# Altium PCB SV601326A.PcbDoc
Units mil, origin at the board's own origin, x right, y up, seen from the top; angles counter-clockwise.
Board outline 2370 x 1275 mil, 4 copper layers (Top Layer, Signal Layer 1, Signal Layer 2, Bottom Layer), stack 61.2 mil thick; 63 components, 27 nets, 159 pads, 280 vias.
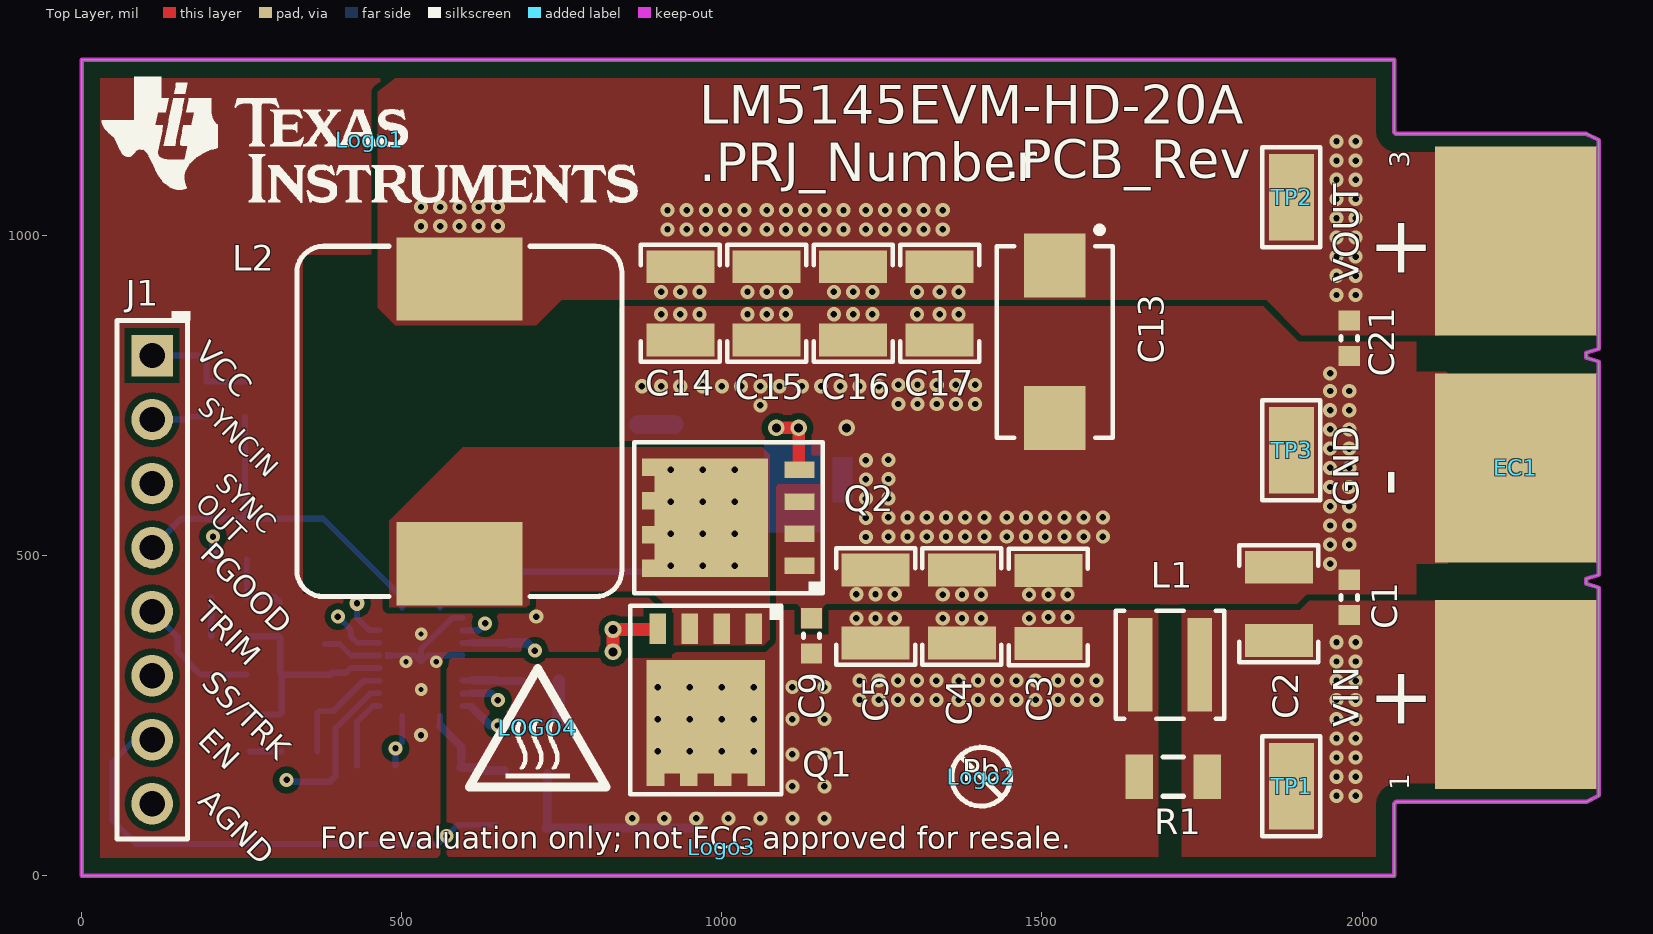
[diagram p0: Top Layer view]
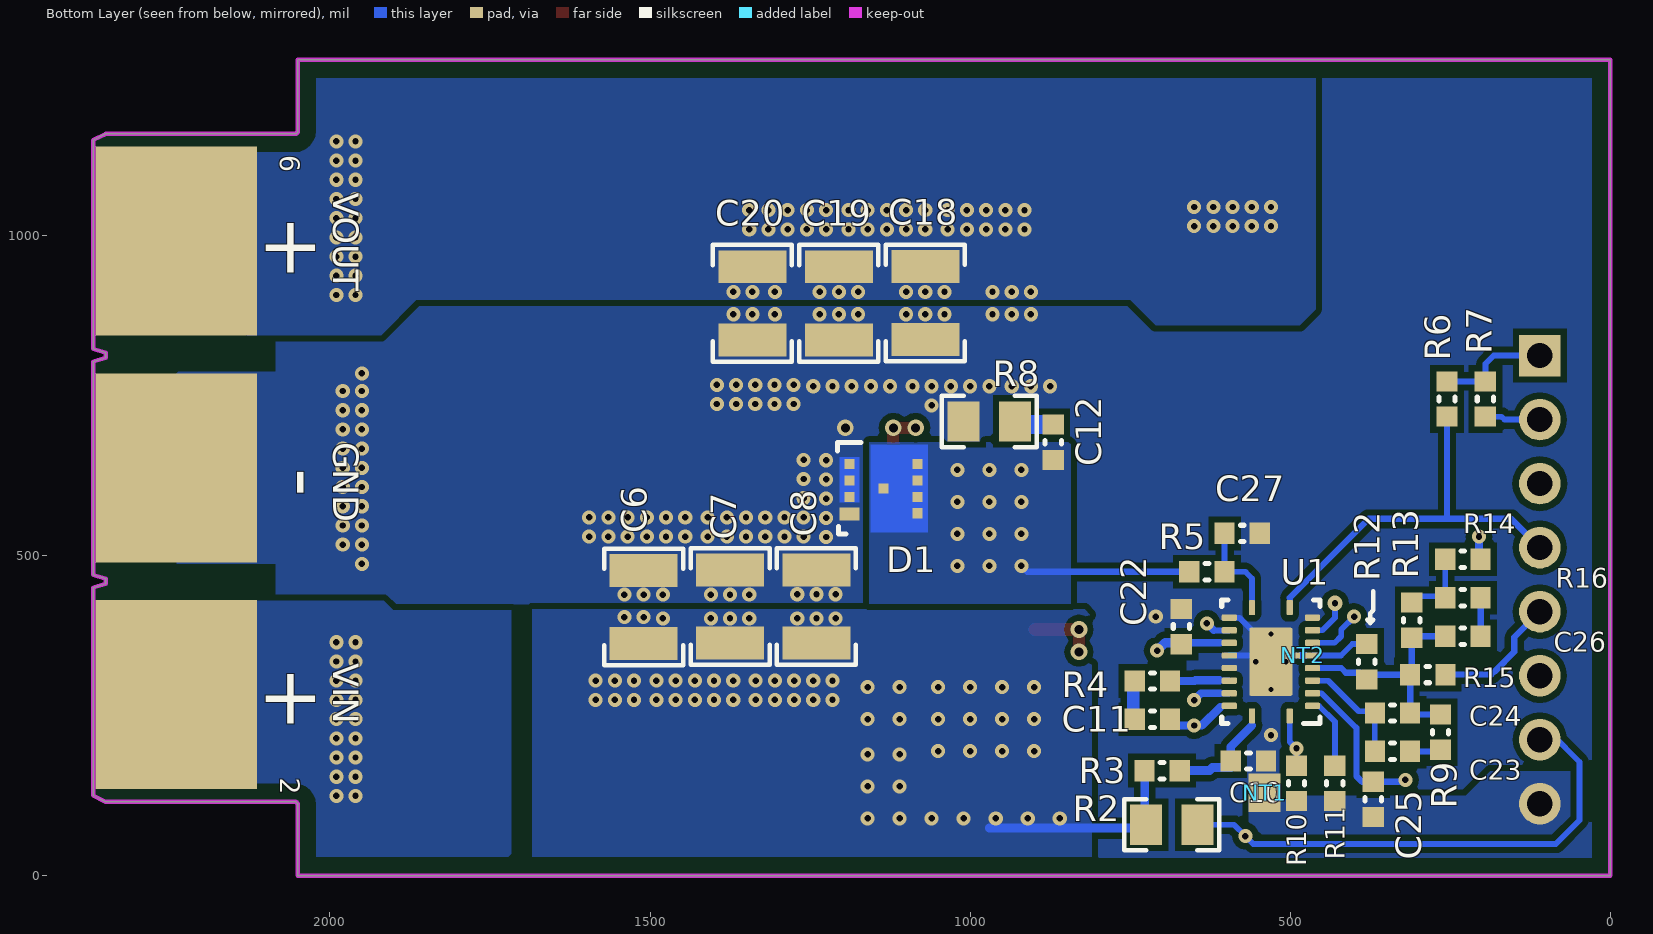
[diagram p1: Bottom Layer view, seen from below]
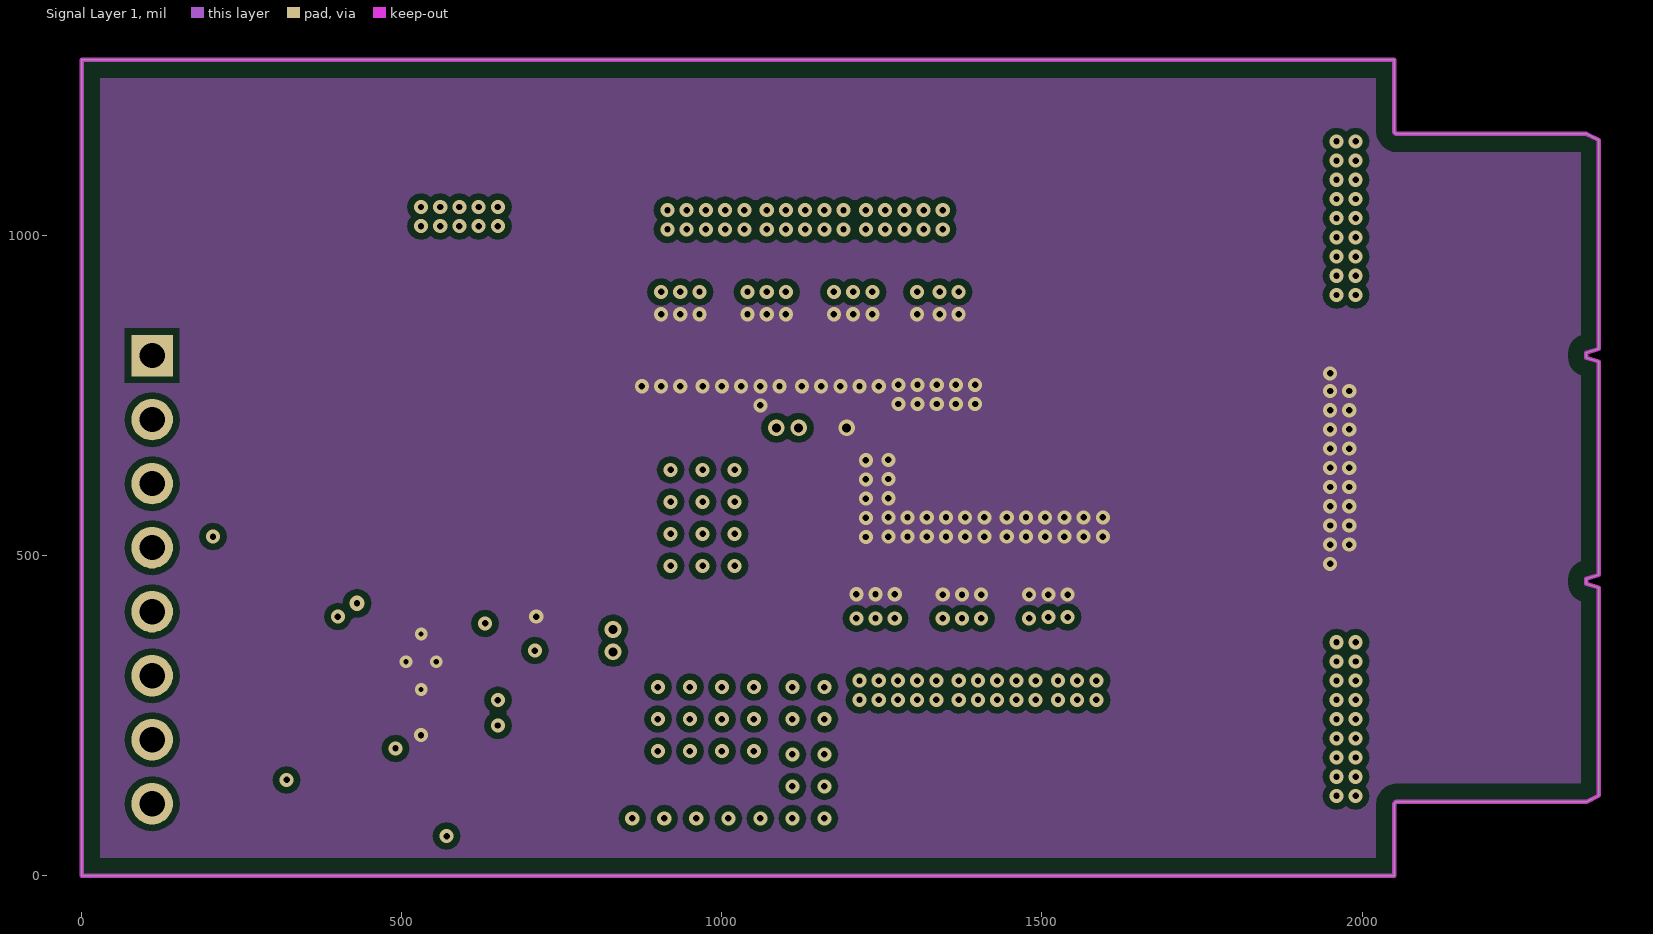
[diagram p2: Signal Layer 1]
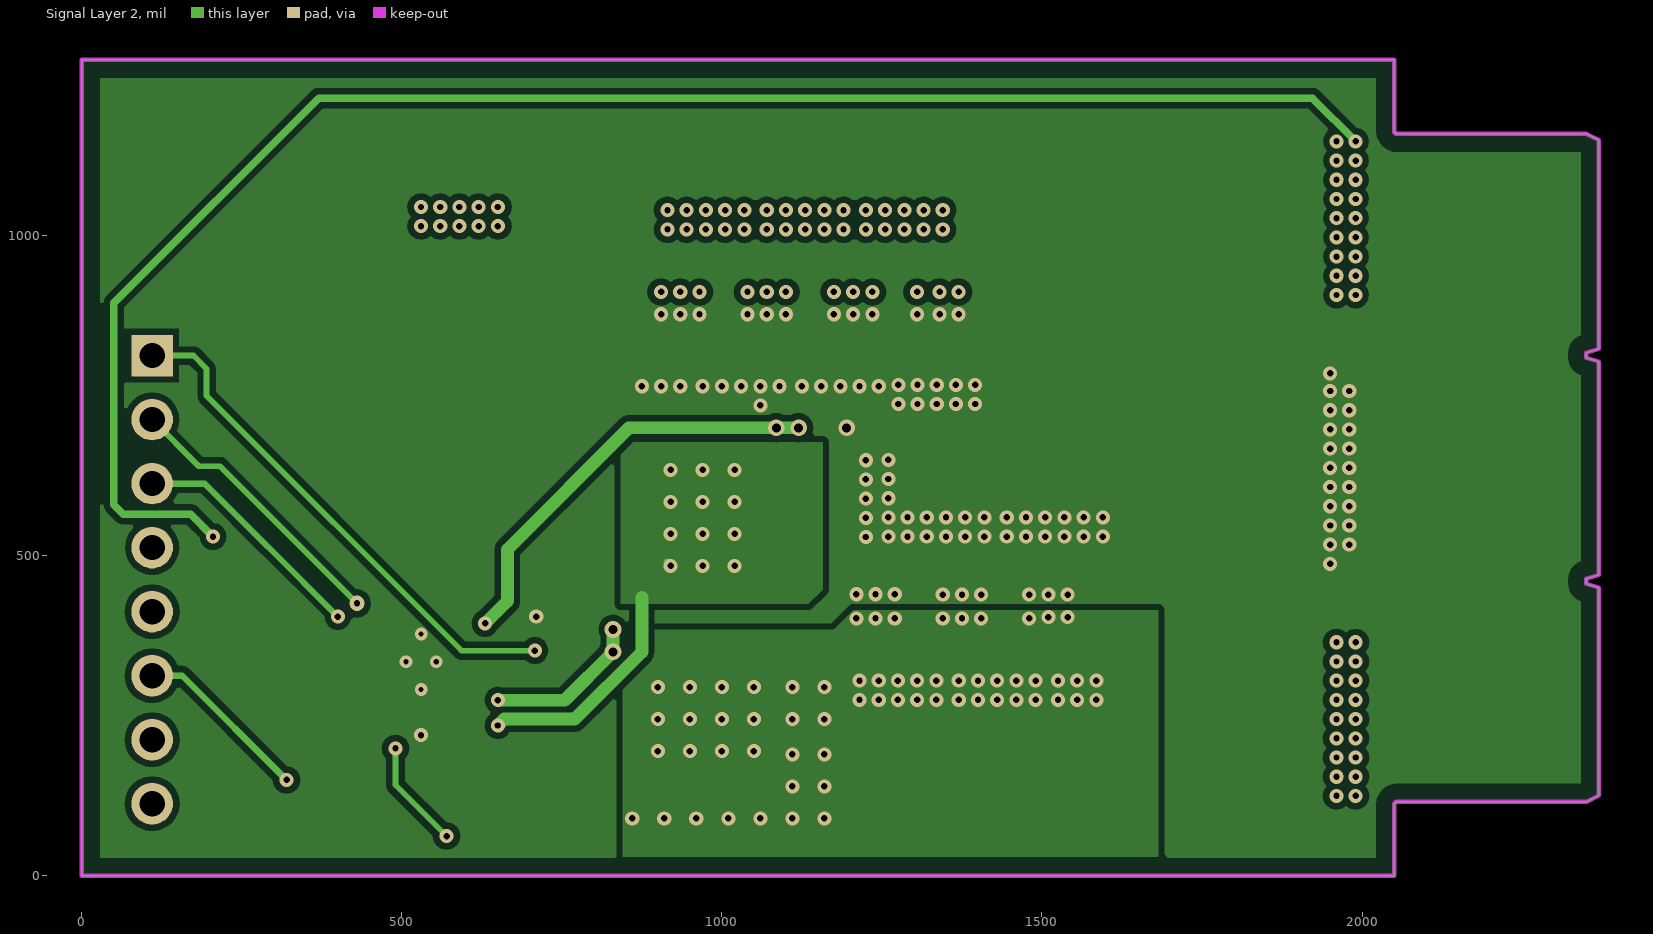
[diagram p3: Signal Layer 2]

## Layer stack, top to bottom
Top Solder: solder mask 0.4, Solder Resist, Dk 3.5
Top Layer: signal copper 2.8
Dielectric1: core 6, FR-4, Dk 4.8
Signal Layer 1: signal copper 2.8
Dielectric 3: prepreg 38, Dk 4.2
Signal Layer 2: signal copper 2.8
Dielectric 2: core 6, FR-4, Dk 4.8
Bottom Layer: signal copper 2.8
Bottom Solder: solder mask 0.4, Solder Resist, Dk 3.5

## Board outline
0,0 2050,0 2050,110.81 cw(c2055.04,110.81) 2055.04,115.85 2350.32,115.85 2370,125.69 2370,450.49 2350.32,456.4 2350.32,464.27 2370,470.18 2370,803.5 2350.32,809.41 2350.32,817.28 2370,823.19 2370,1149.31 2350.32,1159.15 2055.04,1159.15 cw(c2055.04,1164.19) 2050,1164.19 2050,1275 0,1275

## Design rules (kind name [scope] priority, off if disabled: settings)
AcuteAngle [All] p1: minimum=4.50000000000000E+0001 checktracksonly=FALSE
AssemblyTestPointUsage [All] p1: valid=2
Clearance Clearance_EdgeConn [InComponentClass('EdgeConnector') vs OnLayer('Keep-Out Layer')  OR OnLayer ('BoardOutline')] p1: gap=0
Clearance Clearance_Keepouts [((IsTrack Or IsArc) And Not InPoly) And IsFree and IsKeepOut vs ((IsTrack Or IsArc) And Not InPoly) And IsFree and IsKeepOut] p2: gap=0
Clearance Clearance_BoardEdge_MountingHoles [OnCopper and InComponentClass('Mounting Holes') vs IsKeepOut] p3: gap=40
Clearance Clearance_BoardEdge_Poly [OnCopper and InPoly vs IsKeepOut] p4: gap=25
Clearance Clearance_BoardEdge [OnCopper and Not InComponentClass('Logo') and not InComponentClass('FiducialMark') and not InRegion(1000,500,4000,800) and Not IsKeepout vs IsKeepOut] p5: gap=40
Clearance Clearance_Poly [InPolygon] p6: gap=10
Clearance [All] p7: gap=7.87
ComponentClearance ComponentClearance_nETIE10 [HasFootprint('RGY0020B') vs HasFootprint('Net-Tie_10mil')] p1: gap=0 collisioncheckmode=3 verticalgap=0 showdistances=FALSE
ComponentClearance ComponentClearance_nETIE50 [HasFootprint('Net-Tie_50milWide_30milLong') vs HasFootprint('0603L')] p2: gap=0 collisioncheckmode=3 verticalgap=0 showdistances=FALSE
ComponentClearance ComponentClearance_MountingHoles_FiducialMarks [InComponentClass('Mounting Holes') vs InComponentClass('FiducialMark')] p3: gap=50 collisioncheckmode=3 verticalgap=10 showdistances=FALSE
ComponentClearance ComponentClearance_Shunt [InComponentClass('Header') vs InComponentClass('Shunt')] p4: gap=0 collisioncheckmode=3 verticalgap=0 showdistances=FALSE
ComponentClearance ComponentClearance_Logo [InComponentClass('Logo')] p5: gap=50 collisioncheckmode=3 verticalgap=10 showdistances=FALSE
ComponentClearance ComponentClearance_ScrewToNut [(HasFootprint('NY PMS 440 0025 PH')) vs (HasFootprint('Keystone_1902C'))] p6: gap=5 collisioncheckmode=3 verticalgap=10 showdistances=FALSE
ComponentClearance ComponentClearance_MountingHoles [InComponentClass('Mounting Holes')] p7: gap=200 collisioncheckmode=3 verticalgap=100000 showdistances=FALSE
ComponentClearance ComponentClearance_SmallPassives [HasFootprint('0201*') or HasFootprint('0402*') or HasFootprint('0508') or HasFootprint('0603*') or HasFootprint('0612') or HasFootprint('0805*') or HasFootprint('0815*') or HasFootprint('0830*') or HasFootprint('1206*') or HasFootprint('1210*') or HasFootprint('1808*') or HasFootprint('1812*') or HasFootprint('1825*') or HasFootprint('2010*') or HasFootprint('2220*') or HasFootprint('2225*') or HasFootprint('2512*') or HasFootprint('2728*') or HasFootprint('3518*') vs HasFootprint('0201*') or HasFootprint('0402*') or HasFootprint('0508') or HasFootprint('0603*') or HasFootprint('0612') or HasFootprint('0805*') or HasFootprint('0815*') or HasFootprint('0830*') or HasFootprint('1206*') or HasFootprint('1210*') or HasFootprint('1808*') or HasFootprint('1812*') or HasFootprint('1825*') or HasFootprint('2010*') or HasFootprint('2220*') or HasFootprint('2225*') or HasFootprint('2512*') or HasFootprint('2728*') or HasFootprint('3518*')] p8: gap=20 collisioncheckmode=3 verticalgap=10 showdistances=FALSE
ComponentClearance ComponentClearance_THtoSMT [IsThruComponent vs IsSMTComponent] p9: gap=20 collisioncheckmode=3 verticalgap=30 showdistances=FALSE
ComponentClearance ComponentClearance_THtoTH [IsThruComponent vs IsThruComponent] p10: gap=30 collisioncheckmode=3 verticalgap=30 showdistances=FALSE
ComponentClearance [All] p11: gap=30 collisioncheckmode=3 verticalgap=10 showdistances=FALSE
DiffPairsRouting [All] p1: maxlimit=100 minlimit=10 mostfreqgap=10 toplayer_minwidth=15 toplayer_maxwidth=15 toplayer_prefwidth=15 midlayer1_minwidth=15 midlayer1_maxwidth=15 midlayer1_prefwidth=15 midlayer2_minwidth=15 midlayer2_maxwidth=15 midlayer2_prefwidth=15 bottomlayer_minwidth=15 bottomlayer_maxwidth=15 bottomlayer_prefwidth=15 maxuncoupledlength=1000
FabricationTestPointUsage TestPointUsage [All] p1: valid=2 allowmultiple=FALSE
FabricationTestpoint Testpoint [All] p1: side=3 testpointundercomponent=TRUE minsize=40 maxsize=100 preferedsize=60 minholesize=0 maxholesize=40 preferedholesize=32 testpointgrid=1 allowsidetop=TRUE allowsidebottom=TRUE usegrid=TRUE gridtolerance=0.01
FanoutControl Fanout_LCC [IsLCC] p1: bgadir=Out bgaviamode=Centered fanoutstyle=Auto fanoutdirection=Alternating viagrid=1 // Fanout_LCC (Default Rule)
FanoutControl Fanout_BGA [IsBGA] p2: bgadir=Out bgaviamode=Centered fanoutstyle=Auto fanoutdirection=Alternating viagrid=1 // Fanout_BGA (Default Rule)
FanoutControl Fanout_Default [All] p4: bgadir=Out bgaviamode=Centered fanoutstyle=Auto fanoutdirection=Alternating viagrid=1 // Fanout_Default (Default Rule)
FanoutControl Fanout_Small [(CompPinCount < 5)] p5: bgadir=Out bgaviamode=Centered fanoutstyle=Auto fanoutdirection=OutThenIn viagrid=1 // Fanout_Small (Default Rule)
HoleSize [All] p1: absolutevalues=TRUE maxlimit=251 minlimit=7.87 maxpercent=80.000 minpercent=20.000
MinimumAnnularRing MinimumAnnularRing_ThermalPadVias [IsVia and InAnyComponent] p1: minimumring=5.91
MinimumAnnularRing [All] p2: minimumring=5
MinimumSolderMaskSliver MinimumSolderMaskSliver_Logo [InComponentClass('Logo') vs InComponentClass('Logo')] p1: minsoldermaskwidth=0.7
MinimumSolderMaskSliver [All] p2: minsoldermaskwidth=3.94
PlaneConnect [All] p1: planeconnectstyle=Relief reliefexpansion=10 reliefentries=4 reliefconductorwidth=10 reliefairgap=10
PolygonConnect [All] p1: connectstyle=Direct reliefconductorwidth=10 reliefentries=4 polygonreliefangle="90 Angle" airgapwidth=10
RoutingVias ThermalPadVias [IsVia and InAnyComponent] p1: holewidth=7.87 width=19.68 viastyle="Through Hole" minholewidth=7.87 minwidth=19.68 maxholewidth=12.99 maxwidth=23.62
RoutingVias [All] p2: holewidth=10 width=22 viastyle="Through Hole" minholewidth=7.87 minwidth=18 maxholewidth=40 maxwidth=65
ShortCircuit [InNet('AGND') vs InNet('PGND')] p1: allowed=TRUE
SilkToBoardRegionClearance [Not ((IsComment or IsDesignator) And (Hide <> 'False')) and not InRegion(1000,500,4000,800)] p1:
SilkToSilkClearance SilkToSilkClearance_Pb-FreeLogo [(HasFootprint('Pb-Free_Overlay_Medium') OR HasFootprint('Pb-Free_Overlay_Small')) vs (HasFootprint('Pb-Free_Overlay_Medium') OR HasFootprint('Pb-Free_Overlay_Small'))] p1: silktosilkclearance=0
SilkToSilkClearance [All] p2: silktosilkclearance=4
SilkToSolderMaskClearance SilkToComonentPadClearance [IsPad and InAnycomponent] p1: minsilkscreentomaskgap=5 clearancetoexposedcopper=TRUE
SilkToSolderMaskClearance "Silk to Solder Mask Opening_EdgoConn" [InComponentClass('EdgeConnector')] p2: minsilkscreentomaskgap=2 clearancetoexposedcopper=FALSE
SilkToSolderMaskClearance "Silk to Solder Mask Opening" [All] p3: minsilkscreentomaskgap=4 clearancetoexposedcopper=FALSE
SolderMaskExpansion [All] p1: expansion=1.97
UnRoutedNet UnRoutedNet_AGND [InNetClass('GND')] p1:
UnRoutedNet [All] p2:
Width [All] p1: maxlimit=100 minlimit=6 preferedwidth=10 checkconnectedcopper=TRUE
13 further rules are at their usual default settings.

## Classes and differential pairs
component class Header: J1
component class Logo: Logo1
component class SV601326A_HW: Logo1 Logo2 Logo3 LOGO4 ZZ1 ZZ2 ZZ3
component class AssemblyNote: ZZ1 ZZ2 ZZ3
component class SV601326A: C1 C2 C3 C4 C5 C6 C7 C8 C9 C10 C11 C12 C13 C14 C15 C16 C17 C18 C19 C20 C21 C22 C23 C24 C25 C26 C27 D1 EC1 J1 L1 L2 NT1 NT2 Q1 Q2 R1 R2 R3 R4 R5 R6 R7 R8 R9 R10 R11 R12 R13 R14 R15 R16 TP1 TP2 TP3 U1
component class EdgeConnector: EC1

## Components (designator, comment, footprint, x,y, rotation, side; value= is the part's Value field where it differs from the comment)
C1 "GRM188R72A103KA01D" 0603L 1980,435 r90 top
C2 "GRM32DC72A475KE01L" 1210_220 1870,425 r90 top
C3 "GRM32DC72A475KE01L" 1210_220 1510,420 r90 top
C4 "GRM32DC72A475KE01L" 1210_220 1375,420.82 r90 top
C5 "GRM32DC72A475KE01L" 1210_220 1240,420.82 r90 top
C6 "GRM32DC72A475KE01L" 1210_220 1510,420 r90 bottom
C7 "GRM32DC72A475KE01L" 1210_220 1375,420.82 r90 bottom
C8 "GRM32DC72A475KE01L" 1210_220 1240,420.82 r90 bottom
C9 "GRM188R72A103KA01D" 0603L 1140,375 r90 top
C10 "GRM188R72A104KA35D" 0603L 565.16,179.57 r180 bottom
C11 "GRM188R72A104KA35D" 0603L 715.16,244.57 r0 bottom
C12 "C1608C0G2A101F080AA" 0603L 870,677.52 r90 bottom
C13 "220µF" 7343-31 1520,834.41 r270 top
C14 "GRM32ER71A476ME15L" 1210_270 935,894.41 r270 top
C15 "GRM32ER71A476ME15L" 1210_270 1070,894.41 r270 top
C16 "GRM32ER71A476ME15L" 1210_270 1205,894.41 r270 top
C17 "GRM32ER71A476ME15L" 1210_270 1340,894.41 r270 top
C18 "GRM32ER71A476ME15L" 1210_270 1070,895 r270 bottom
C19 "GRM32ER71A476ME15L" 1210_270 1205,894.41 r270 bottom
C20 "GRM32ER71A476ME15L" 1210_270 1340,894.41 r270 bottom
C21 "GRM188R72A103KA01D" 0603L 1980,840 r270 top
C22 "EMK107BB7225MA-T" 0603L 669.85,389.57 r90 bottom
C23 "GRM188R71E562KA01D" 0603l 340.16,194.57 r180 bottom
C24 "GRM1885C1H151JA01D" 0603l 340.16,254.57 r180 bottom
C25 "C1608X7R1H473K080AA" 0603L 370.16,119.57 r270 bottom
C26 "GRM1885C1H182JA01D" 0603l 230.16,374.57 r0 bottom
C27 "GRM1885C2A150JA01D" 0603L 575,535 r0 bottom
D1 "100V" PowerFLAT_3_3x3_3 1135,605 r180 bottom
EC1 "EDGE_CONN_6651712-1" TE_EDGE_CONN_6651712-1 2370,637.5 r90 top
J1 "PEC08SAAN" SULLINS_PEC08SAAN 110,462.85 r270 top
L1 "XAL4040-822MEB" XAL4040 1700,330 r180 top
L2 "CMLS136E-3R3MS" CMLS136E 590,710 r90 top
Logo1 "Texas Instruments" TI_Stacked_Overlay_Small 450,1150 r0 top
Logo2 "Pb-Free Symbol" Pb-Free_Overlay_Small 1405,155 r0 top
Logo3 "FCC disclaimer" FCC_disclaimer 1000,45 r0 top
LOGO4 "CAUTION HOT SURFACE" IEC_HotSurface_Small 712.36,231.77 r0 top
NT1 "Net-Tie" Net-Tie_50milWide_30milLong 540,130 r90 bottom net-tie
NT2 "Net-Tie" Net-Tie_10mil 480,344.41 r180 bottom net-tie
Q1 "BSC117N08NS5ATMA1" PG-TDSON-8 975,275 r270 top
Q2 "BSC037N08NS5ATMA1" PG-TDSON-8 1010,559.41 r180 top
R1 "CRCW120610R0FKEA" 1206L 1705,155 r180 top
R2 "CRCW0805301KFKEA" 0805_HV 685,80 r0 bottom
R3 "CRCW06032R20JNEA" 0603L 700.16,164.57 r0 bottom
R4 "CRCW06030000Z0EA" 0603L 715.16,304.57 r0 bottom
R5 "CRCW0603422RFKEA" 0603l 630,475 r0 bottom
R6 "CRCW060320K0FKEA" 0603L 255,745 r270 bottom
R7 "CRCW060320K0FKEA" 0603L 195,745 r270 bottom
R8 "RC0805FR-072R2L" 0805_HV 970,710 r180 bottom
R9 "CRCW060310K0FKEA" 0603l 265.16,224.57 r270 bottom
R10 "CRCW060318K2FKEA" 0603L 490.16,144.57 r90 bottom
R11 "CRCW060346K4FKEA" 0603l 430.16,144.57 r90 bottom
R12 "CRCW06033K83FKEA" 0603l 380.16,334.57 r270 bottom
R13 "CRCW060320K0FKEA" 0603l 310.16,399.57 r90 bottom
R14 "CRCW060349R9FKEA" 0603L 230.16,494.57 r180 bottom
R15 "CRCW060329K4FKEA" 0603l 285.16,314.57 r0 bottom
R16 "CRCW06031K00FKEA" 0603l 230.16,434.57 r0 bottom
TP1 "5015" Testpoint_Keystone_Miniature 1890,140 r270 top
TP2 "5015" Testpoint_Keystone_Miniature 1890,1060 r270 top
TP3 "5015" Testpoint_Keystone_Miniature 1890,665 r270 top
U1 "LM5145RGYR" RGY0020B 530.16,334.57 r0 bottom
ZZ1 "These assemblies are ESD sensitive, ESD precautions shall be observed." AssemblyNote 185,2779.11 r0 top
ZZ2 "These assemblies must be clean and free from flux and all contaminants. Use of no clean flux is not acceptable." AssemblyNote 185,2690.56 r0 top
ZZ3 "These assemblies must comply with workmanship standards IPC-A-610 Class 2, unless otherwise specified." AssemblyNote 185,2602 r0 top

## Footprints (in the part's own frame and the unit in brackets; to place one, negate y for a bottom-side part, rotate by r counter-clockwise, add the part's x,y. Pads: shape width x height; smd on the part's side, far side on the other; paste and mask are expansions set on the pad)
0603L [mm] "0603 from SM-752 data"
  rect 0.8x0.85 smd: 1(-0.7,0) 2(0.7,0)
  silkscreen extent -0.07,-0.33 0.07,0.33, body extent -0.87,-0.47 0.87,0.47, height 1
0603l [mm] "0603 from SM-752 data"
  rect 0.8x0.85 smd: 1(-0.7,0) 2(0.7,0)
  silkscreen extent -0.07,-0.33 0.07,0.33, body extent -0.87,-0.47 0.87,0.47, height 1
0805_HV [mil] "0805 with 30mil clearance between pads"
  rect 50x63 smd: 1(-40,0) 2(40,0)
  silkscreen extent -74,-40 74,40, body extent -43,-29 43,29, height 57
1206L [mm] "1206 from SM-752 data"
  rect 1.1x1.75 smd: 1(-1.35,0) 2(1.35,0)
  silkscreen extent -0.4,-0.77 0.4,0.77, body extent -1.7,-0.9 1.7,0.9, height 1.35
1210_220 [mm] "1210"
  rect 1.3x2.7 smd: 1(-1.45,0) 2(1.45,0)
  silkscreen extent -2.32,-1.57 2.32,1.57, body extent -1.7,-1.35 1.7,1.35, height 2.2
1210_270 [mm] "1210"
  rect 1.3x2.7 smd: 1(-1.45,0) 2(1.45,0)
  silkscreen extent -2.32,-1.57 2.32,1.57, body extent -1.7,-1.35 1.7,1.35, height 2.7
7343-31 [mm] "Medium Density based on Kemet T495 dimensions"
  rect 2.55x2.45 smd: 1(-3.025,0) 2(3.025,0)
  silkscreen extent -4.56,-2.3 3.8,2.3, body extent -3.8,-2.3 3.8,2.3, height 3.1
AssemblyNote [mil] "Assembly Note"
CMLS136E [mm] "CYNTEC"
  rect 3.3x5 smd: 1(-5.65,0) 2(5.65,0)
  silkscreen extent -6.95,-6.45 6.95,6.45, body extent -6.9,-6.4 6.9,6.4, height 6.5
FCC_disclaimer [mil]
IEC_HotSurface_Small [mil]
  silkscreen extent -107,-93 107,92
Net-Tie_10mil [mil] "10mil net tie, no solder mask opening, no solder paste"
  rect 10x10 smd paste-5 mask-5: 1(-10,0) 2(10,0)
  Top Layer region: -6,5 6,5 6,-5 -6,-5
Net-Tie_50milWide_30milLong [mil] "50mil net tie, no solder mask opening, no solder paste"
  rect 30x50 smd paste-20 mask-20: 1(-15,0) 2(15,0)
Pb-Free_Overlay_Small [mil]
  silkscreen extent -46,-46 46,46
PG-TDSON-8 [mm] "Infineon recommended land pattern"
  rect 1.2x0.65 smd: 1(-2.825,1.905) 2(-2.825,0.635) 3(-2.825,-0.635) 4(-2.825,-1.905)
  rect 0.5x0.7 smd: 5(3.175,-2) 6(3.175,-0.675) 7(3.175,0.675) 8(3.175,2)
  rect 4.5x4.7 smd paste-2.25: 9(0.675,0)
  silkscreen extent -3.74,-3 3.74,3, body extent -3.18,-2.89 3.18,2.9, height 1.1
PowerFLAT_3_3x3_3 [mm] "SMD, 8-Leads, Body 3.3x3.3mm"
  rect 0.4x0.4 smd: 1(-1.35,0.975) 2(-1.35,0.325) 3(-1.35,-0.325) 5(1.35,-0.975) 6(1.35,-0.325) 7(1.35,0.325) 8(1.35,0.975) 9(0,0)
  rect 0.8x0.52 smd: 4(-1.35,-1.01)
  Top Layer region: -0.53,1.75 1.75,1.75 1.75,-1.75 -0.53,-1.75
  Top Layer region: -1.75,1.25 -0.95,1.25 -0.95,-0.54 -1.75,-0.54
  silkscreen extent -1.83,-1.8 -0.9,1.83, body extent -1.7,-1.7 1.7,1.7, height 1.06
RGY0020B [mm] "QFN, 20-Leads, Body 4.5x3.5mm, Pitch 0.5mm, Thermal Pad 2.7x1.7mm"
  rrect40% 0.25x0.6 smd: 1(-0.75,2.15) 10(-0.75,-2.15) 11(0.75,-2.15) 20(0.75,2.15)
  rrect40% 0.6x0.25 smd: 2(-1.65,1.75) 3(-1.65,1.25) 4(-1.65,0.75) 5(-1.65,0.25) 6(-1.65,-0.25) 7(-1.65,-0.75) 8(-1.65,-1.25) 9(-1.65,-1.75) 12(1.65,-1.75) 13(1.65,-1.25) 14(1.65,-0.75) 15(1.65,-0.25) 16(1.65,0.25) 17(1.65,0.75) 18(1.65,1.25) 19(1.65,1.75)
  rrect6% 1.7x2.7 smd paste-1.4: 21(0,0)
  silkscreen extent -1.95,-2.45 1.95,2.45, body extent -1.75,-2.25 1.75,2.25, height 0.9
SULLINS_PEC08SAAN [mm] "SULLINS"
  rect 1.65x1.65 hole 1: 1(-8.89,0)
  round 1.65 hole 1: 2(-6.35,0) 3(-3.81,0) 4(-1.27,0) 5(1.27,0) 6(3.81,0) 7(6.35,0) 8(8.89,0)
  silkscreen extent -10.67,-1.4 10.29,1.52, body extent -10.29,-1.33 10.29,1.33, height 8.38
TE_EDGE_CONN_6651712-1 [mm] "Card Edge Footprint, 3x2"
  rect 7.5x6.4 smd paste-6: 1(-9,3.3) 3(0,3.3) 5(9,3.3)
  rect 7.5x6.4 smd far side paste-6: 2(-9,3.3) 4(0,3.3) 6(9,3.3)
Testpoint_Keystone_Miniature [mil] "Miniature SMT test point"
  rect 135x70 smd: 1(0,0)
  silkscreen extent -78,-46 78,45, body extent -52,-20 52,20, height 61
TI_Stacked_Overlay_Small [mil]
  silkscreen extent -418,-98 418,98
XAL4040 [mil] "Coilcraft XAL4040 7/18/12"
  rect 38x146 smd: 1(-46.5,0) 2(46.5,0)
  silkscreen extent -85,-85 85,85, body extent -84,-84 84,84, height 161

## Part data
C1 C9 C21: "CAP, CERM, 0.01 µF, 100 V, +/- 10%, X7R, 0603"
C2 C3 C4 C5 C6 C7 C8: "CAP, CERM, 4.7 µF, 100 V, +/- 10%, X7S, 1210"
C10 C11: "CAP, CERM, 0.1 µF, 100 V, +/- 10%, X7R, 0603"
C12: "CAP, CERM, 100 pF, 100 V, +/- 1%, C0G/NP0, 0603"
C13: library part ECASD60J227M010K00, "CAP ALUM POLY 220UF 20% 6.3V SMD"
C14 C15 C16 C17 C18 C19 C20: "CAP, CERM, 47 µF, 10 V, +/- 20%, X7R, 1210"
C22: "CAP, CERM, 2.2 µF, 16 V, +/- 10%, X7R, 0603"
C23: "CAP, CERM, 5600 pF, 25 V, +/- 10%, X7R, 0603"
C24: "CAP, CERM, 150 pF, 50 V, +/- 5%, C0G/NP0, 0603"
C25: "CAP, CERM, 0.047 µF, 50 V, +/- 10%, X7R, 0603"
C26: "CAP, CERM, 1800 pF, 50 V, +/- 5%, C0G/NP0, 0603"
C27: "CAP, CERM, 15 pF, 100 V, +/- 5%, C0G/NP0, 0603"
D1: library part STPS6M100DEE-TR, "Diode, Schottky, 100 V, 6 A, 8-PowerTDFN"
EC1: "Card Edge Footprint, 3x2"
J1: "Header, 100mil, 8x1, Tin, TH"
L1: "Inductor, Shielded, Composite, 8.2 µH, 3.4 A, 0.0608 ohm, SMD"
L2: "Inductor, 3.3 µH, 20 A, 0.0044 ohm, SMD"
Logo1: library part TI_Logo, "Texas Instrument Corporate Signature"
Logo2: library part Pb-Free
Logo3: library part FCC_disclaimer, "FCC_disclaimer"
LOGO4: library part IEC_HotSurface, "IEC 61010-1 Hot Surface Warning"
NT1 NT2: "Single point connection between nets."
Q1: "MOSFET, N-CH, 80 V, 49 A, PG-TDSON-8"
Q2: "MOSFET N-CH 80V 100A 8TDSON"
R1: "RES, 10.0, 1%, 0.25 W, 1206"
R2: "RES, 301 k, 1%, 0.125 W, 0805"
R3: "RES, 2.2, 5%, 0.1 W, 0603"
R4: "RES, 0, 5%, 0.1 W, 0603"
R5: "RES, 422, 1%, 0.1 W, 0603"
R6 R7 R13: "RES, 20.0 k, 1%, 0.1 W, 0603"
R8: "RES, 2.20, 1%, 0.125 W, 0805"
R9: "RES, 10.0 k, 1%, 0.1 W, 0603"
R10: "RES, 18.2 k, 1%, 0.1 W, 0603"
R11: "RES, 46.4 k, 1%, 0.1 W, 0603"
R12: "RES, 3.83 k, 1%, 0.1 W, 0603"
R14: "RES, 49.9, 1%, 0.1 W, 0603"
R15: "RES, 29.4 k, 1%, 0.1 W, 0603"
R16: "RES, 1.00 k, 1%, 0.1 W, 0603"
TP1 TP2 TP3: "Test Point, Miniature, SMT"
U1: "Wide Input Range Synchronous Buck Controller, RGY0020B"
ZZ1 ZZ2 ZZ3: library part AssemblyNote

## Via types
v1: diameter 22, hole 10, Top Layer to Bottom Layer, tented both sides, 246 vias
v2: diameter 22, hole 10, Top Layer to Bottom Layer, 24 vias
v3: diameter 19.68, hole 7.87, Top Layer to Bottom Layer, 4 vias
v4: diameter 26, hole 14, Top Layer to Bottom Layer, 3 vias
v5: diameter 26, hole 14, Top Layer to Bottom Layer, tented both sides, 2 vias
v6: diameter 24, hole 10, Top Layer to Bottom Layer, tented both sides, 1 vias

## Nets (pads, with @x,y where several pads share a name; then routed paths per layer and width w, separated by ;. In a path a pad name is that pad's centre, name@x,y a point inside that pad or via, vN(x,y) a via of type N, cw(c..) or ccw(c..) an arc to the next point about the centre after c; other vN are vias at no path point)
AGND: NT2.2 R12.1 U1.6 | length 92.4
  Bottom Layer w9: R12.1 402.87,362.13 420.59,344.41 U1.6
AGND*: C25.2 J1.8 NT1.1 R10.1 R11.1
HO: Q1.4 U1.18 | length 409.4
  Top Layer w20: v5(830,350) v4(830,385) Q1.4@898.78,385
  Signal Layer 2 w20: v1(650.16,274.57) 754.57,274.57 v5(830,350) v4(830,385)
  Bottom Layer w9.4: U1.18 609.55,285.35
  Bottom Layer w12: 609.55,285.35 639.37,285.35 v1(650.16,274.57)
NetC10_1: C10.1 R3.1 U1.20 | length 163.5
  Bottom Layer w9.4: 559.69,235.04 U1.20
  Bottom Layer w12: C10.1@592.72,169.57 C10.1 C10.1@592.72,185.79
  Bottom Layer w13: 559.69,235.04 592.72,202.01 C10.1@592.72,185.79
  Bottom Layer w14: C10.1@592.72,169.57 621.16,169.57 626.16,164.57 R3.1@660.16,164.57
NetC11_1: C11.1 C12.1 D1.5 D1.6 D1.7 D1.8 D1.9 L2.1 Q1.1 Q1.2 Q1.3 Q2.5 Q2.6 Q2.7 Q2.8 Q2.9 R5.2 U1.19 | length 716.9
  Signal Layer 2 w12: v2@914.41,490 v2(920,484.41)
  Signal Layer 2 w20: v1(650,235) 660,245 770,245 875,350 875,435
  Bottom Layer w9.4: U1.19 609.06,265.67
  Bottom Layer w10: R5.2 910.59,475 v2(920,484.41)
  Bottom Layer w13: 609.16,263.98 638.14,235 v1@640.16,235 ; v1(650,235) C11.1@678.03,235
  other v2: 970,484.41 1020,484.41 920,534.41 970,534.41 1020,534.41 920,584.41 970,584.41 1020,584.41 920,634.41 970,634.41 1020,634.41
NetC11_2: C11.2 R4.2 | length 61.1
  Bottom Layer w20: R4.2@745.16,304.57 745.16,247.13 C11.2@747.72,244.57
NetC12_2: C12.2 R8.2 | length 55.1
  Bottom Layer w30: C12.2 R8.2@925.08,705.08
NetC23_1: C23.1 C24.1 U1.4 | length 174.4
  Bottom Layer w9: C23.1 C24.1 ; C24.1@370.52,257.36 392.95,257.36 440.63,305.04 U1.4
NetC23_2: C23.2 R9.2 | length 50
  Bottom Layer w9: R9.2@262.6,194.57 C23.2
NetC24_2: C24.2 C26.2 R9.1 R12.2 R13.1 R15.2 U1.5 | length 375
  Bottom Layer w9: R9.1@260.16,252.13 C24.2@310.16,252.13 ; 412.95,317.36 420.32,324.72 U1.5
  Bottom Layer w10: C26.2 307.6,374.57 R13.1 R15.2@310.16,317.13 ; C24.2@312.72,254.68 R15.2 387.72,314.57 390.51,317.36 412.95,317.36
NetC25_1: C25.1 J1.6 U1.3 | length 525
  Signal Layer 2 w10: J1.6 157.15,312.85 v1(320,150)
  Bottom Layer w9: 397.11,231.52 450.94,285.35 U1.3
  Bottom Layer w10: v1(320,150) 322.87,147.13 C25.1 387.72,147.13 396.34,155.75 396.34,230.75 397.11,231.52
NetC26_1: C26.1 R16.1 | length 60
  Bottom Layer w10: C26.1 R16.1
NetC27_2: C27.2 R5.1 U1.11 | length 152.4
  Bottom Layer w9: U1.11 559.69,464.69 570,475 R5.1 C27.2@602.44,534.88
NetJ1_2: J1.2 R7.2 U1.8 | length 591.5
  Signal Layer 2 w9: J1.2 182.85,640 215.81,640 v6(430,425.81)
  Bottom Layer w9: J1.2 165.35,712.85 169.94,717.44 R7.2 ; v6(430,425.81) 430,403.38 449.6,383.78 U1.8
NetJ1_3: J1.3 U1.7 | length 464.3
  Signal Layer 2 w9: 290,515 v1(400,405)
  Signal Layer 2 w10: J1.3 192.15,612.85 290,515
  Bottom Layer w9: v1(400,405) 420.16,384.84 420.16,374.57 430.63,364.09 U1.7
NetJ1_4: J1.4 R6.2 U1.10 | length 635.2
  Bottom Layer w9: 255,557.85 R6.2
  Bottom Layer w9.4: U1.10 500.63,434.37
  Bottom Layer w10: J1.4 155,557.85 255,557.85 377.15,557.85 500.63,434.37
NetJ1_5: J1.5 R15.1 | length 201.7
  Bottom Layer w9: 180,320 185.43,314.57 R15.1
  Bottom Layer w10: J1.5 150,372.85 150,350 180,320
NetJ1_7: J1.7 R2.1 R10.2 U1.1 | length 1017.6
  Signal Layer 2 w9: v1@490.16,189.57 490.16,142.13 v1(570,62.28)
  Bottom Layer w9: J1.7@90,220 48,178 48,87 85,50 557.72,50 v1(570,62.28) 587.72,80 R2.1 ; R10.2 v1(490.16,199.19) 500.63,209.66 U1.1
NetQ2_4: Q2.4 U1.13 | length 802.1
  Top Layer w20: v5(1085,700) v4(1120,700) Q2.4@1120,635.63
  Signal Layer 2 w20: v1(630.16,394.57) 665,429.41 665,510 855,700 v5(1085,700) v4(1120,700)
  Bottom Layer w9.4: U1.13 619.37,383.78
  Bottom Layer w12: 619.61,384.01 v1(630.16,394.57)
NetR4_1: R4.1 U1.17 | length 94.6
  Bottom Layer w9: R4.1@692.13,305.04 R4.1@692.6,304.57
  Bottom Layer w9.4: U1.17 610.33,305.04 611.02,305.73
  Bottom Layer w13: 610.33,305.73 611.02,305.73 647.81,305.73 648.97,304.57 R4.1
NetR11_2: R11.2 U1.2 | length 114
  Bottom Layer w9: R11.2 430.16,240.7 455.12,265.67 U1.2
NetR13_2: R13.2 R14.1 R16.2 | length 114.1
  Bottom Layer w9: R16.2 R14.1 ; R16.2@260.16,437.01 300.28,437.01 R13.2
PGND: C1.2 C2.2 C3.2 C4.2 C5.2 C6.2 C7.2 C8.2 C9.2 C10.2 C13.2 C14.2 C15.2 C16.2 C17.2 C18.2 C19.2 C20.2 C21.2 C22.2 C27.1 D1.1 D1.2 D1.3 D1.4 EC1.3 EC1.4 NT1.2 NT2.1 Q2.1 Q2.2 Q2.3 R8.1 TP3.1 U1.9 U1.12 U1.15 U1.16 U1.21 | length 218.4
  Bottom Layer w9: NT2.1@490.16,344.41 520.16,344.57 U1.21 ; U1.15 540,344.41 U1.21 ; U1.12 579.06,403.46 530.16,354.57 U1.21
  other v1: 530,220 710,405 1345,439.41 1375,439.41 1405,439.41 1480,439.41 1510,439.41 1540,439.41 1210,440 1240,440 1270,440 1950,487.5 1950,517.5 1980,517.5 1225,529.41 1260,530 1290,530 1320,530 1350,530 1380,530 1410,530 1445,530 1475,530 1505,530 1535,530 1565,530 1595,530 1950,547.5 1980,547.5 1225,559.41 1260,560 1290,560 1320,560 1350,560 1380,560 1410,560 1445,560 1475,560 1505,560 1535,560 1565,560 1595,560 1950,577.5 1980,577.5 1225,589.41 1260,590 1950,607.5 1980,607.5 1225,619.41 1260,620 1950,637.5 1980,637.5 1225,649.41 1260,650 1950,667.5 1980,667.5 1950,697.5 1980,697.5 1950,727.5 1980,727.5 1060,735 1275.59,737.17 1305.59,737.17 1335.59,737.17 1365.59,737.17 1395.59,737.17 1950,757.5 1980,757.5 875,765 905,765 935,765 970,765 1000,765 1030,765 1060,765 1090,765 1125,765 1155,765 1185,765 1215,765 1245,765 1275.59,767.17 1305.59,767.17 1335.59,767.17 1365.59,767.17 1395.59,767.17 1950,785 905,877.41 935,877.41 965,877.41 1040,877.41 1070,877.41 1100,877.41 1175,877.41 1205,877.41 1235,877.41 1305,877.41 1340,877.41 1369.85,877.41
  other v3: 530.16,291.26 506.54,334.57 553.78,334.57 530.16,377.87
  other v4: 1195,700
V+: C1.1 C2.1 EC1.1 EC1.2 L1.1 R1.1 TP1.1
  other v1: 1960,125 1990,125 1960,155 1990,155 1960,185 1990,185 1960,215 1990,215 1960,245 1990,245 1960,275 1990,275 1960,305 1990,305 1960,335 1990,335 1960,365 1990,365
VCC: C22.1 J1.1 R6.1 R7.1 U1.14 | length 1112.5
  Signal Layer 2 w9: J1.1 174.4,812.85 195,792.24 195,750 593.05,351.95 v1(707.77,351.95)
  Bottom Layer w9: J1.1 182.15,812.85 195,800 R7.1 R6.1
  Bottom Layer w9.4: U1.14 609.68,364.09
  Bottom Layer w12: 609.68,364.09 667.76,364.09 C22.1
  Bottom Layer w15: C22.1@667.29,364.57 695.16,364.57 v1(707.77,351.95)
VIN: C3.1 C4.1 C5.1 C6.1 C7.1 C8.1 C9.1 L1.2 Q1.5 Q1.6 Q1.7 Q1.8 Q1.9 R1.2 R2.2 R3.2 | length 330
  Bottom Layer w14: R2.2@725.16,74.57 R2.2@727.18,74.57 ; R3.2@727.18,160.11 R2.2@727.18,74.57 ; 969.57,74.57 R2.2@727.18,74.57
  other v1: 860,90 910,90 960,90 1010,90 1060,90 1110,90 1160,90 1110,140 1160,140 1110,190 1160,190 1110,245 1160,245 1215,275 1245,275 1275,275 1305,275 1335,275 1370,275 1400,275 1430,275 1460,275 1490,275 1525,275 1555,275 1585,275 1110,295 1160,295 1215,305 1245,305 1275,305 1305,305 1335,305 1370,305 1400,305 1430,305 1460,305 1490,305 1525,305 1555,305 1585,305 1210,402.41 1240,402.41 1270,402.41 1345,402.41 1375,402.41 1405,402.41 1480,402.41 1510,404.41 1540,404.41
  other v2: 900,195 950,195 1000,195 1050,195 900,245 950,245 1000,245 1050,245 900,295 950,295 1000,295 1050,295
VOUT: C13.1 C14.1 C15.1 C16.1 C17.1 C18.1 C19.1 C20.1 C21.1 EC1.5 EC1.6 L2.2 R14.2 TP2.1 | length 2627.6
  Signal Layer 2 w12: v1(205,530) 170,565 65,565 50,580 50,895 370,1215 1922.5,1215 v1(1990,1147.5)
  Bottom Layer w12: R14.2 205,496.97 v1(205,530)
  other v1: 1960,907.5 1990,907.5 905,912.41 935,912.41 965,912.41 1040,912.41 1070,912.41 1100,912.41 1175,912.41 1205,912.41 1235,912.41 1305,912.41 1340,912.41 1369.85,912.41 1960,937.5 1990,937.5 1960,967.5 1990,967.5 1960,997.5 1990,997.5 915,1010 945,1010 975,1010 1005,1010 1035,1010 1070,1010 1100,1010 1130,1010 1160,1010 1190,1010 1225,1010 1255,1010 1285,1010 1315,1010 1345,1010 530,1015 560,1015 590,1015 620,1015 650,1015 1960,1027.5 1990,1027.5 915,1040 945,1040 975,1040 1005,1040 1035,1040 1070,1040 1100,1040 1130,1040 1160,1040 1190,1040 1225,1040 1255,1040 1285,1040 1315,1040 1345,1040 530,1045 560,1045 590,1045 620,1045 650,1045 1960,1057.5 1990,1057.5 1960,1087.5 1990,1087.5 1960,1117.5 1990,1117.5 1960,1147.5

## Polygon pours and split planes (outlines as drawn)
VOUT on Top Layer "M1 Board Outline-No Net" (solid, pour order 1083): 2120,845 1905,845 1850.07,899.93 750.01,900.01 710,860 490,860 462.5,887.5 462.5,1225.28 494.29,1250 2030,1250 2120,1160
PGND on Top Layer "Bottom Layer-No Net" (solid, pour order 1084): 2050,0 0,0 0,1275 2050,1275 2050,1159.15 2136.27,1159.15 2132.42,115.85 2050,115.85
NetC11_1 on Top Layer "Top Layer-No Net 2" (solid, pour order 1080): 1075,370 1075,455 1075,658.74 1063.74,670 1019.09,670 828.43,670 595,670 480,555 480,445 480,420 700,420 700,445 890,445 925,410 925,360 1065,360
VIN on Top Layer "Top Layer-No Net 1" (solid, pour order 1082): 1681.77,30 570,30 570,340 922.8,340 922.8,415 1681.77,415
V+ on Top Layer "Top Layer-No Net" (solid, pour order 1081): 2125,430 1917.68,430 1902.68,415 1718.64,415 1718.64,30 2045,30 2045,130 2125,130
VOUT on Bottom Layer "M1 Board Outline-No Net" (solid, pour order 1095): 2130,845 1920,845 1865.03,899.97 750.05,900.05 710,860 485,860 460,885 460,1282.5 457.5,1285 2009.15,1285 2130,1164.15
VIN on Bottom Layer "Top Layer-No Net 1" (solid, pour order 1094): 1802.5,30 810,30 810,405 821.25,416.25 1802.5,416.25
V+ on Bottom Layer "Top Layer-No Net" (solid, pour order 1093): 2123.18,430 1915.86,430 1900.86,415 1716.82,415 1716.82,30 2043.18,30 2043.18,130 2123.18,130
PGND on Bottom Layer "Bottom Layer-No Net" (solid, pour order 1096): 2050,0 0,0 0,1275 2050,1275 2050,1159.15 2241.93,1159.15 2238.08,115.85 2050,115.85
AGND* on Bottom Layer "Signal Layer 2-No Net" (solid, pour order 1091): 565,125 565,85 550,70 530,50 28.75,50 28.75,125 28.75,163.63 187.37,163.63 226,125
NetC11_1 on Bottom Layer "Bottom Layer-No Net 1" (solid, pour order 1092): 843,677.55 1157.24,677.13 1157.24,425 843,425
PGND on Signal Layer 1 "Signal Layer 1-PGND" (solid, pour order 1087): 2050,0 0,0 0,1275 2045,1275 2045,1159.15 2365,1159.15 2365,115.85 2050,115.85
NetC11_1 on Signal Layer 2 "SignalLayer2 -Q2Thermal" (solid, pour order 1088): 842.12,677.55 1157.24,677.13 1157.24,447.24 1135,425 842.12,425
PGND on Signal Layer 2 "Signal Layer 2-No Net 1" (solid, pour order 1090): 0,1275 2050,1275 2050,1176.81 2370,1176.81 2370,955 2370,360 2370,115.85 2055.04,115.85 2055.04,0 0,0
VIN on Signal Layer 2 "Inner Layer2-Vin" (solid, pour order 1089): 1681.77,30 845,30 845,384.77 1174.77,384.77 1205,415 1681.77,415

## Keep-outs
Keep-Out Layer:
  the board outline again, w7
  text ".Layer_Name" at 577,-908.49 h60

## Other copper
Top Layer:
  pour cut-out: 1683.9,424.42 1683.9,30 1716.82,30 1716.82,422.34 1714.74,424.42
  pour cut-out: 345,440 345,970 447.5,970 447.5,850 715,850 755,890 840,890 840,675 580,675 475,570 475,440
  pour cut-out: 2240,842.5 2240,787.5 2085,787.5 2085,792.5 2085,842.5
  pour cut-out: 2245,487.5 2245,432.5 2085,432.5 2085,437.5 2085,487.5
  text ".Layer_Name" at 577,-908.49 h60
Signal Layer 1:
  text ".Layer_Name" at 575,-910 h60
Signal Layer 2:
  text ".Layer_Name" at 575,-905 h60
Bottom Layer:
  pour cut-out: 1683.9,424.42 1683.9,30 1716.82,30 1716.82,422.34 1714.74,424.42
  pour cut-out: 2255,487.5 2255,432.5 2085,432.5 2085,437.5 2085,487.5
  pour cut-out: 2245,842.5 2245,787.5 2085,787.5 2085,792.5 2085,842.5
  text ".Layer_Name" at 577,-908.49 h60

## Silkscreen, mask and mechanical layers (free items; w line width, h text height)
Top Overlay:
  text "LM5145EVM-HD-20A" at 965,1175 h60
  text ".PCB_Rev" at 1440,1090 h60
  text ".PRJ_Number" at 965,1085 h60
  text "+" at 2010,942.5 h90
  text "VOUT" at 1995,927.5 h40 r90
  text "VCC" at 175,815 h35 r315
  text "SYNCIN" at 180,730 h30 r315
  text "-" at 2080,592.5 h90 r90
  text "SYNC / OUT" at 175.44,578.92 h30 r315
  text "GND" at 1995,577.5 h40 r90
  text "PGOOD" at 182.91,500 h35 r315
  text "TRIM" at 176.85,407.83 h35 r315
  text "SS/TRK" at 185.43,299.78 h35 r315
  text "+" at 2010,237.5 h90
  text "VIN" at 1995,232.5 h40 r90
  text "EN" at 180,210 h35 r315
  text "AGND" at 180,115 h35 r315
  text ".Layer_Name" at 577,-908.49 h60
Bottom Overlay:
  lines w7: 370,445 370,415 375,410 375,395 ; 375,395 380,400 370,400 375,395
  text "VOUT" at 1995,1067.5 h40 r90
  text "+" at 2010,942.5 h90
  text "GND" at 1995,677.5 h40 r90
  text "-" at 2080,592.5 h90 r90
  text "VIN" at 1995,332.5 h40 r90
  text "+" at 2010,237.5 h90
  text ".Layer_Name" at 577,-908.49 h60
Top Paste:
  text ".Layer_Name" at 577,-908.49 h60
Bottom Paste:
  text ".Layer_Name" at 577,-908.49 h60
Top Solder:
  text ".Layer_Name" at 577,-908.49 h60
  text ".Layer_Name" at 577,-908.49 h60
Bottom Solder:
  text ".Layer_Name" at 577,-908.49 h60
Drill Guide:
  text ".Layer_Name" at 577,-908.49 h60
M1 Board Outline:
  lines w7: 2050,110 2050,0 0,0 0,1275 2050,1275 2050,1165 ; 2050,110.81 cw(c2055.04,110.81) 2055.04,115.85 2350.32,115.85 2370,125.69 2370,450.49 2350.32,456.4 2350.32,464.27 2370,470.18 2370,803.5 2350.32,809.41 2350.32,817.28 2370,823.19 2370,1149.31 2350.32,1159.15 2055.04,1159.15 cw(c2055.04,1164.19) 2050,1164.19
  text ".Layer_Name" at 577,-908.49 h60
M2 Board Dimensions:
  rectangle: 0,-325 125,-200
  rectangle: 125,-450 500,-325
  lines w7: 0,-325 1000,-325 ; 125,-450 125,-200 ; 250,-450 250,-200 ; 500,-450 500,-200 ; 750,-450 750,-200 ; 0,-450 1000,-450 1000,-200 0,-200 0,-450
  text ".Layer_Name" at 577,-908.49 h60
M3 3D STEP Top:
  text ".Layer_Name" at 577,-908.49 h60
M4 3D STEP Bottom:
  text ".Layer_Name" at 577,-908.49 h60
M5 Assembly Top:
  lines w10: -292,-980.17 6308,-980.17 ; -292,-776.83 6310,-776.83 ; -292,-573.5 -292,-1183.5 3713,-1183.5 6310,-1183.5 6310,-573.5 -291.5,-573.5 -291.5,-1183.5 1284,-1183.5 ; 2173,-1183.5 2173,-573.5 ; 3440,-776.83 3440,-573.5 ; 4280,-776.83 4280,-573.5 ; 4902,-1190 4902,-987.17
  text "COMPONENTS MARKED 'DNP' SHOULD NOT BE POPULATED." at 1153.5,-368.5 h60
  text "ASSEMBLY VARIANT:" at 1153,-484 h60
  text ".VariantName" at 2189,-484 h60
  text "PCB VIEWED FROM TOP SIDE" at -228.5,-705.67 h60
  text "BOARD #:" at 2248,-705.67 h60
  text ".PRJ_Number" at 2793.5,-705.67 h60
  text "REV:" at 3638,-705.67 h60
  text ".PCB_Rev" at 3929.5,-705.67 h60
  text "SVN REV:" at 4476,-705.67 h60
  text ".VersionControl_RevNumber" at 4982,-705.67 h60
  text "TID #:" at 2248,-909 h60
  text ".TID" at 2793.5,-909 h60
  text "PLOT NAME =" at -228.5,-1114.34 h60
  text ".plot_File_Name" at 577,-1114.34 h60
  text "GENERATED    :" at 2250,-1114.34 h60
  text ".Print_Date" at 3119.5,-1114.34 h60
  text ".Print_Time" at 3848.5,-1114.34 h60
  text "TEXAS INSTRUMENTS" at 5113,-1114.34 h60
M6 Assembly Bottom:
  lines w10: -292.5,-777.33 6309.5,-777.33 ; -290.5,-980.67 6309.5,-980.67 ; 1115.5,-1190.5 1115.5,-987.67 ; 1737.5,-777.33 1737.5,-574 ; 2577.5,-777.33 2577.5,-574 ; 3844.5,-1184 3844.5,-574 ; 4733.5,-1184 6309,-1184 6309,-574 -292.5,-574 -292.5,-1184 2304.5,-1184 6309.5,-1184 6309.5,-574
  text "COMPONENTS MARKED 'DNP' SHOULD NOT BE POPULATED." at 6102,-368 h60
  text ".VariantName" at 5058,-484 h60
  text "ASSEMBLY VARIANT:" at 6097,-484 h60
  text ".VersionControl_RevNumber" at 1035.5,-706.17 h60
  text "SVN REV:" at 1541.5,-706.17 h60
  text ".PCB_Rev" at 2088,-706.17 h60
  text "REV:" at 2379.5,-706.17 h60
  text ".PRJ_Number" at 3224,-706.17 h60
  text "BOARD #:" at 3769.5,-706.17 h60
  text "PCB VIEWED FROM BOTTOM SIDE" at 6246,-706.17 h60
  text ".TID" at 3224,-909.5 h60
  text "TID #:" at 3769.5,-909.5 h60
  text "TEXAS INSTRUMENTS" at 904.5,-1114.84 h60
  text ".Print_Time" at 2169,-1114.84 h60
  text ".Print_Date" at 2898,-1114.84 h60
  text "GENERATED    :" at 3767.5,-1114.84 h60
  text ".plot_File_Name" at 5440.5,-1114.84 h60
  text "PLOT NAME =" at 6246,-1114.84 h60
M9 Title Sheet:
  drawing of 57 lines, arcs and shapes, not listed
  text "1" at 739.84,7986.5 h70
  text "2" at 3235.5,7986.5 h70
  text "3" at 5724.84,7986.5 h70
  text "4" at 8231.51,7986.5 h70
  text "5" at 10730.5,7986.5 h70
  text "6" at 13235.5,7986.5 h70
  text "A" at -416.5,6843.5 h70
  text "A" at 14383.5,6843.5 h70
  text "B" at -416.5,4463.5 h70
  text "B" at 14383.5,4463.5 h70
  text "C" at -416.5,2088.5 h70
  text "C" at 14383.5,2088.5 h70
  text "PROJECT TITLE:" at 11343.5,227.5 h45
  text ".PRJ_Title" at 11393.5,94.17 h70
  text "DESIGNED FOR:" at 11343.5,-73.5 h45
  text ".PRJ_Customer" at 11393.5,-213.5 h70
  text "D" at -416.5,-281.5 h70
  text "D" at 14383.5,-281.5 h70
  text "FILE NAME:" at 11343.5,-373.5 h45
  text ".PCB_File_Name_No_Path" at 11393.5,-493.5 h70
  text "Texas Instruments (TI) and/or its licensors do not warrant the accuracy or completeness of this specification" at 6374,-655.34 h45
  text "ENGINEER:" at 11343.5,-663.5 h45
  text "LAYOUT BY:" at 12848.5,-663.5 h45
  text "or any information contained therein. TI and/or its licensors do not warrant that this design will meet" at 6329.01,-768 h45
  text ".PRJ_Engineer" at 11393.5,-818.49 h70
  text ".PCB_Layout" at 12899,-818.49 h70
  text "the specifications, will be suitable for your application or fit for any particular purpose, or will operate in" at 6329.01,-880.67 h45
  text ".Layer_Name" at 577,-908.49 h60
  text "ALTIUM DESIGNER VERSION:" at 12848.5,-973.5 h45
  text "an implementation. TI and/or its licensors do not warrant that the design is production worthy. You should" at 6329.01,-993.33 h45
  text "completely validate and test your design implementation to confirm the system functionality for your application." at 6374,-1106 h45
  text ".print_Scale" at 11393.5,-1106.83 h70
  text ".Application_BuildNumber" at 12899,-1106.83 h70
  text "1" at 739.84,-1313.5 h70
  text "2" at 3235.5,-1313.5 h70
  text "3" at 5724.84,-1313.5 h70
  text "4" at 8231.51,-1313.5 h70
  text "5" at 10730.5,-1313.5 h70
  text "6" at 13235.5,-1313.5 h70
M10 Fab Notes:
  drawing of 173 lines, arcs and shapes, not listed
  text "DESIGN INFORMATION" at 12377.02,6151 h60
  text "MIN. TRACK WIDTH:" at 11732.46,5971 h60
  text "8" at 12828.7,5971 h60
  text "MIL" at 12983.46,5971 h60
  text "MIN. CLEARANCE:" at 11732.46,5839 h60
  text "0.2" at 12768.7,5839 h60
  text "mm" at 12983.46,5839 h60
  text "MIN. VIA PAD SIZE:" at 11732.46,5707 h60
  text "24" at 12798.71,5707 h60
  text "MIL" at 12983.46,5707 h60
  text "0.05mm (2MIL)" at 12427.46,5565.29 h60
  text "MINIMUM ANNULAR RING" at 11403.23,5561 h60
  text "EXTERNAL" at 13135.46,5561 h60
  text "PER" at 11603.23,5443 h60
  text "IPC-D-275 CLASS 2 LEVEL C" at 11823.23,5443 h60
  text "MIL, HOLES" at 13311.46,5330.71 h60
  text "+/-" at 12919,5330 h60
  text "+/-" at 13773,5330 h60
  text "REGISTRATION TOLERANCES:" at 11403.23,5325 h60
  text "METAL" at 12603,5325 h60
  text "5" at 13179.2,5325 h60
  text "3" at 14012.2,5325 h60
  text "MIL" at 14128.46,5325 h60
  text "+/-" at 13773,5212 h60
  text "HOLE SIZE TOLERANCE (UNLESS OTHERWISE SPECIFIED):" at 11403.23,5207 h60
  text "3" at 14012.2,5207 h60
  text "MIL" at 14128.46,5207 h60
  text "MATERIAL:" at 11328.46,4997.54 h60
  text "FR-4 High Tg" at 12314.9,4857.21 h60
  text "FR-408" at 11749.46,4848.64 h60
  text "OTHER" at 13237.46,4848.64 h60
  text "X" at 12160,4845 h60
  text "62 MIL (1.6mm) +/-10%" at 12069.56,4685.92 h60
  text "THICKNESS:" at 11403.23,4681.64 h60
  text "X" at 11941.4,4681.64 h60
  text "OTHER" at 13354.46,4681.64 h60
  text "TOLERANCE:" at 11403.23,4523.64 h60
  text "X" at 12242.53,4523.64 h60
  text "ANSI IPC-6012 TYPE 3 CLASS 2" at 12429.48,4523.64 h60
  text "OTHER +/-" at 12429.46,4367.64 h60
  text "BOW & TWIST:" at 11403.23,4210.64 h60
  text "X" at 12242.53,4210.64 h60
  text "ANSI IPC-6012 TYPE 3 CLASS 2" at 12429.48,4210.64 h60
  text "OTHER +/-" at 12429.46,4052.13 h60
  text "DRILLING:" at 11328.46,3913.64 h60
  text "REFERENCE:" at 11403.23,3796.64 h60
  text "X" at 12051.46,3796.64 h60
  text "AS SHOWN" at 12238.46,3796.64 h60
  text "X" at 12952.46,3796.64 h60
  text "NC_DRILL FILES" at 13089.46,3796.64 h60
  text "PTH COPPER THICKNESS:" at 11403.23,3638.64 h60
  text "X" at 12533.46,3638.64 h60
  text "20-30 um" at 12670.46,3638.64 h60
  text "OTHER" at 13387.46,3638.64 h60
  text "BOARD FINISH:" at 11328.46,3479.64 h60
  text "SILKSCREEN:" at 11483.68,3361.64 h60
  text "X" at 12432.46,3361.64 h60
  text "TOP" at 12558.46,3361.64 h60
  text "X" at 12942.46,3361.64 h60
  text "BOTTOM" at 13069.46,3361.64 h60
  text "SILKSCREEN COLOR:" at 11483.68,3194.64 h60
  text "X" at 12431.42,3194.64 h60
  text "WHITE" at 12558.46,3194.64 h60
  text "OTHER" at 13069.46,3194.64 h60
  text "X" at 12562.42,3035.44 h60
  text "GREEN" at 12689.46,3035.44 h60
  text "OTHER" at 13307.46,3035.44 h60
  text "SOLDER RESIST COLOR:" at 11483.68,3024.64 h60
  text "X" at 12562.42,2865.44 h60
  text "MATTE" at 12689.46,2865.44 h60
  text "SEMI-GLOSS" at 13307,2864.8 h60
  text "IMMERSION GOLD (ENIG)" at 12389.46,2676.92 h60
  text "ENEPIG" at 13727,2673.64 h60
  text "SURFACE FINISH:" at 11328.46,2672.64 h60
  text "X" at 12202.51,2672.64 h60
  text "IMM. TIN/SILVER OR EQUIV" at 11658,2515.64 h60
  text "OTHER" at 13089.46,2515.64 h60
  text "ARRAY/PANEL:" at 11328.46,2336.64 h60
  text "CUT AND TRIM PER M1 BOARD OUTLINE" at 12389.46,2332.35 h60
  text "X" at 12205,2185 h60
  text "N.C. ROUTE" at 12389.46,2180.64 h60
  text "V. SCORE" at 13255.46,2180.64 h60
  text "CERTIFICATION:" at 11328.46,2043.64 h60
  text "MATERIALS AND WORKMANSHIP FOR ALL PCBS" at 12053.46,2043.64 h60
  text "TO MEET OR EXCEED THE REQUIREMENTS OF:" at 12053.46,1945.64 h60
  text "X" at 11679.96,1809.13 h60
  text "ANSI IPC-A-600F CLASS ->" at 11818.96,1809.13 h60
  text "X" at 13458.02,1809.13 h60
  text "2" at 13576.96,1809.14 h60
  text "1" at 13261.96,1807.64 h60
  text "3" at 13930.96,1807.64 h60
  text "X" at 12494.02,1649.64 h60
  text "RoHS" at 12630.96,1649.64 h60
  text "OTHER" at 13275.36,1649.64 h60
  text "PER ORDER" at 13672.42,1649.64 h60
  text "ALL BOARDS MUST MEET OR EXCEED UL94-V0 REQUIREMENTS." at 11356,1484 h60
  text "PCB MUST BEAR THE UL94V-0 UL REGISTERED MATERIAL ID NUMBER" at 11356,1364 h60
  text "ADDITIONAL REQUIREMENTS:" at 11328.46,1190.64 h60
  text "MICROSECTION:" at 11403.23,1075.64 h60
  text "YES" at 12308.96,1075.64 h60
  text "REQUIRED" at 13170.46,919.49 h60
  text "BARE BOARD ELEC. TEST:" at 11403.23,916.64 h60
  text "NONE" at 12708.96,916.64 h60
  text "X" at 13043.46,916.64 h60
  text "PER ORDER" at 13762.46,916.64 h60
  text ".Layer_Name" at 577,-908.49 h60
M11 Gerber Information:
  lines w10: -292,-980.17 6308,-980.17 ; -292,-776.83 6310,-776.83 ; -292,-573.5 -292,-1183.5 3713,-1183.5 6310,-1183.5 6310,-573.5 -291.5,-573.5 -291.5,-1183.5 1284,-1183.5 ; 2173,-1183.5 2173,-573.5 ; 3440,-776.83 3440,-573.5 ; 4280,-776.83 4280,-573.5 ; 4902,-1190 4902,-987.17
  text "ALL ARTWORK VIEWED FROM TOP SIDE" at -228.5,-705.67 h60
  text "BOARD #:" at 2248,-705.67 h60
  text ".PRJ_Number" at 2793.5,-705.67 h60
  text "REV:" at 3638,-705.67 h60
  text ".PCB_Rev" at 3929.5,-705.67 h60
  text "SVN REV:" at 4476,-705.67 h60
  text ".VersionControl_RevNumber" at 4982,-705.67 h60
  text "LAYER NAME =" at -228.5,-908.49 h60
  text "TID #:" at 2248,-909 h60
  text ".TID" at 2793.5,-909 h60
  text "PLOT NAME =" at -228.5,-1114.34 h60
  text ".plot_File_Name" at 577,-1114.34 h60
  text "GENERATED    :" at 2250,-1114.34 h60
  text ".Print_Date" at 3119.5,-1114.34 h60
  text ".Print_Time" at 3848.5,-1114.34 h60
  text "TEXAS INSTRUMENTS" at 5113,-1114.34 h60
M12 Stackup:
  drawing of 295 lines, arcs and shapes, not listed
  text "Layer" at 9797.84,7780 h60
  text "Name" at 10207.76,7780 h60
  text "Material" at 11147.5,7780 h60
  text "Thickness" at 12007.26,7780 h60
  text "Constant" at 12657.1,7780 h60
  text "Board Layer Stack" at 13226.96,7780 h60
  text "1" at 9797.84,7660 h60
  text "Top Overlay" at 10207.76,7660 h60
  text "2" at 9797.84,7540 h60
  text "Top Solder" at 10207.76,7540 h60
  text "Solder Resist" at 11147.5,7540 h60
  text "0.40mil" at 12007.26,7540 h60
  text "3.5" at 12657.1,7540 h60
  text "3" at 9797.84,7420 h60
  text "Top Layer" at 10207.76,7420 h60
  text "Copper" at 11147.5,7420 h60
  text "2.80mil" at 12007.26,7420 h60
  text "4" at 9797.84,7300 h60
  text "Dielectric1" at 10207.76,7300 h60
  text "FR-4" at 11147.5,7300 h60
  text "6.00mil" at 12007.26,7300 h60
  text "4.8" at 12657.1,7300 h60
  text "5" at 9797.84,7180 h60
  text "Signal Layer 1" at 10207.76,7180 h60
  text "Copper" at 11147.5,7180 h60
  text "2.80mil" at 12007.26,7180 h60
  text "6" at 9797.84,7060 h60
  text "Dielectric 3" at 10207.76,7060 h60
  text "38.00mil" at 12007.26,7060 h60
  text "4.2" at 12657.1,7060 h60
  text "7" at 9797.84,6940 h60
  text "Signal Layer 2" at 10207.76,6940 h60
  text "Copper" at 11147.5,6940 h60
  text "2.80mil" at 12007.26,6940 h60
  text "8" at 9797.84,6820 h60
  text "Dielectric 2" at 10207.76,6820 h60
  text "FR-4" at 11147.5,6820 h60
  text "6.00mil" at 12007.26,6820 h60
  text "4.8" at 12657.1,6820 h60
  text "9" at 9797.84,6700 h60
  text "Bottom Layer" at 10207.76,6700 h60
  text "Copper" at 11147.5,6700 h60
  text "2.80mil" at 12007.26,6700 h60
  text "10" at 9797.84,6580 h60
  text "Bottom Solder" at 10207.76,6580 h60
  text "Solder Resist" at 11147.5,6580 h60
  text "0.40mil" at 12007.26,6580 h60
  text "3.5" at 12657.1,6580 h60
  text "11" at 9797.84,6460 h60
  text "Bottom Overlay" at 10207.76,6460 h60
  text ".Layer_Name" at 577,-908.49 h60
M13 Component Bodies Top:
  text ".Layer_Name" at 577,-908.49 h60
M14 Component Bodies Bottom:
  text ".Layer_Name" at 577,-908.49 h60
M15 Courtyards Top:
  text ".Layer_Name" at 577,-908.49 h60
M16 Courtyards Bottom:
  text ".Layer_Name" at 577,-908.49 h60
Drill Drawing:
  lines w10: 5656.04,2377.56 5711.23,2377.56 5683.63,2322.37 5656.04,2377.56 ; 5656.04,2446.55 5711.23,2446.55 5711.23,2501.74 5656.04,2501.74 5656.04,2446.55 ; 5656.04,2584.52 5669.83,2584.52 5683.63,2570.72 5697.43,2584.52 5711.23,2584.52 5697.43,2598.32 5711.23,2612.12 5697.43,2612.12 5683.63,2625.91 5669.83,2612.12 5656.04,2612.12 5669.83,2598.32 5656.04,2584.52 ; 5656.04,2694.9 5683.63,2708.7 5711.23,2694.9 5697.43,2722.5 5711.23,2750.09 5683.63,2736.29 5656.04,2750.09 5669.83,2722.5 5656.04,2694.9 ; 5667.07,2590.04 5675.35,2590.04 5683.63,2581.76 5691.91,2590.04 5700.19,2590.04 5691.91,2598.32 5700.19,2606.6 5691.91,2606.6 5683.63,2614.88 5675.35,2606.6 5667.07,2606.6 5675.35,2598.32 5667.07,2590.04 ; 5667.07,2705.94 5683.63,2714.22 5700.19,2705.94 5691.91,2722.5 5700.19,2739.05 5683.63,2730.77 5667.07,2739.05 5675.35,2722.5 5667.07,2705.94
  lines w12: 5606,2285.12 7583.93,2285.12 ; 5606,2781.82 7583.93,2781.82 ; 5943.86,2160.94 5943.86,2906 ; 6275.86,2160.94 6275.86,2906 ; 6912.42,2160.94 6912.42,2906 ; 7171.53,2160.94 7171.53,2906 ; 5606,2160.94 7583.93,2160.94 7583.93,2906 5606,2906 5606,2160.94
  text "Symbol" at 5680.51,2819.08 h72
  text "Quantity" at 5981.11,2819.08 h72
  text "Finished Hole Size" at 6313.12,2819.08 h72
  text "Plated" at 6949.67,2819.08 h72
  text "Hole Type" at 7208.78,2819.08 h72
  text "4" at 5981.11,2694.9 h60
  text "7.87mil (0.200mm)" at 6313.12,2694.9 h60
  text "PTH" at 6949.67,2694.9 h60
  text "Round" at 7208.78,2694.9 h60
  text "271" at 5981.11,2570.72 h60
  text "10.00mil (0.254mm)" at 6313.12,2570.72 h60
  text "PTH" at 6949.67,2570.72 h60
  text "Round" at 7208.78,2570.72 h60
  text "5" at 5981.11,2446.55 h60
  text "14.00mil (0.356mm)" at 6313.12,2446.55 h60
  text "PTH" at 6949.67,2446.55 h60
  text "Round" at 7208.78,2446.55 h60
  text "8" at 5981.11,2322.37 h60
  text "39.37mil (1.000mm)" at 6313.12,2322.37 h60
  text "PTH" at 6949.67,2322.37 h60
  text "Round" at 7208.78,2322.37 h60
  text "288 Total" at 5981.11,2198.2 h60
  text ".Layer_Name" at 577,-908.49 h60

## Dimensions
0,-450 to 1000,-450 on M2 Board Dimensions
0,0 to 2050,0 on M2 Board Dimensions
0,0 to 0,1275 on M2 Board Dimensions
2370,1149.31 to 2050,1275 on M2 Board Dimensions
2350.32,1159.15 to 2350.32,115.85 on M2 Board Dimensions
